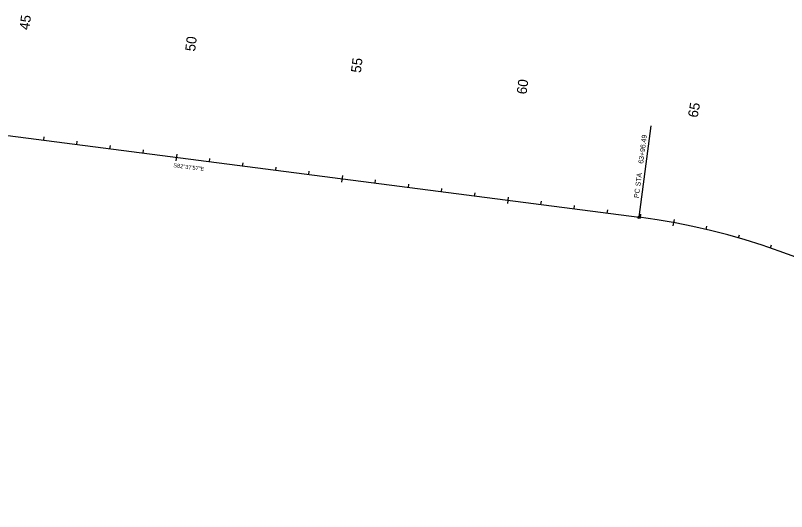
# Model space of a CAD drawing. Extents: x 996549 to 1005839, y 697562 to 701048.
# Drawn here: x 1001194 to 1003501, y 699277 to 700761 of the extents above; entities that cross this region are included whole.
import ezdxf

# ---------------------------------------------------------------- set-up
doc = ezdxf.new("R2010")
doc.units = 0
for name, color, linetype in [('Default', 7, 'Continuous'), ('Geom_Scratch', 7, 'Continuous'), ('Modeling-Corridor Boundary-Preliminary', 7, 'Continuous'), ('Modeling-Proposed subsurface-aggregate base', 7, 'Continuous'), ('Modeling-Proposed subsurface-concrete pavement', 7, 'Continuous'), ('Modeling-Proposed subsurface-incidental aggregate base', 7, 'Continuous'), ('Modeling-Proposed surface-concrete pavement', 7, 'Continuous'), ('Modeling-Template Range-Preliminary', 7, 'Continuous')]:
    doc.layers.add(name, color=color, linetype=linetype)

msp = doc.modelspace()

# ---------------------------------------------------------------- linework, layer by layer
at = {"layer": 'Default'}
msp.add_line((1000405.9, 700500.6), (1003059.9, 700157.4), dxfattribs=at)
msp.add_arc((1002803.4, 698173.9), 2000, 33.4817, 82.6324, dxfattribs=at)
at = {"layer": 'Geom_Scratch'}
msp.add_line((1000405.9, 700500.6), (1003059.9, 700157.4), dxfattribs=at)
msp.add_arc((1002803.4, 698173.9), 2000, 33.4817, 82.6324, dxfattribs=at)
at = {"layer": 'Modeling-Corridor Boundary-Preliminary'}
for p, q in [((1001676.2, 700346.4), (1001673.6, 700326.5)), ((1002172.1, 700282.3), (1002169.5, 700262.4)), ((1002667.9, 700218.1), (1002665.4, 700198.3)), ((1003163.9, 700151.3), (1003160.3, 700131.6))]:
    msp.add_line(p, q, dxfattribs=at)
at = {"layer": 'Modeling-Proposed subsurface-aggregate base'}
for p, q in [((1001278.2, 700387.8), (1001279.5, 700397.7)), ((1001377.4, 700375), (1001378.7, 700384.9)), ((1001476.6, 700362.1), (1001477.9, 700372.1)), ((1001575.7, 700349.3), (1001577, 700359.2)), ((1001774.1, 700323.7), (1001775.4, 700333.6)), ((1001873.3, 700310.9), (1001874.6, 700320.8)), ((1001972.4, 700298), (1001973.7, 700307.9)), ((1002071.6, 700285.2), (1002072.9, 700295.1)), ((1002270, 700259.6), (1002271.3, 700269.5)), ((1002369.1, 700246.7), (1002370.4, 700256.6)), ((1002468.3, 700233.9), (1002469.6, 700243.8)), ((1002567.5, 700221.1), (1002568.8, 700231)), ((1002765.8, 700195.4), (1002767.1, 700205.4)), ((1002865, 700182.6), (1002866.3, 700192.5)), ((1002964.2, 700169.8), (1002965.5, 700179.7)), ((1003063.4, 700157), (1003064.7, 700166.9)), ((1003260, 700121.1), (1003262.3, 700130.8)), ((1003356.8, 700095.9), (1003359.6, 700105.5)), ((1003452.2, 700065.8), (1003455.4, 700075.3))]:
    msp.add_line(p, q, dxfattribs=at)
at = {"layer": 'Modeling-Proposed subsurface-concrete pavement'}
for p in [(1003059.9, 700157.4), (1003095.3, 700431.1)]:
    msp.add_line(p, (1003095.3, 700431.1), dxfattribs=at)
msp.add_circle((1003059.9, 700157.4), 3.96, dxfattribs=at)

# ---------------------------------------------------------------- texts
at = {"layer": 'Modeling-Proposed subsurface-incidental aggregate base'}
msp.add_text('S82°37\'57"E', height=12, rotation=352.6324, dxfattribs=at).set_placement((1001665.5, 700307.5))
at = {"layer": 'Modeling-Proposed surface-concrete pavement'}
for s, p in [('63+96.49', (1003071.8, 700317.1)), (' STA ', (1003062.3, 700243.7)), ('PC', (1003058.5, 700214.3))]:
    msp.add_text(s, height=15, rotation=82.6324, dxfattribs=at).set_placement(p)
at = {"layer": 'Modeling-Template Range-Preliminary'}
for s, rotation, p in [('45', 82.6324, (1001235, 700716.4)), ('50', 82.6324, (1001730.9, 700652.3)), ('55', 82.6324, (1002226.8, 700588.2)), ('60', 82.6324, (1002722.6, 700524.1)), ('65', 79.667, (1003234.4, 700454))]:
    msp.add_text(s, height=30, rotation=rotation, dxfattribs=at).set_placement(p)

doc.saveas('drawing.dxf')
